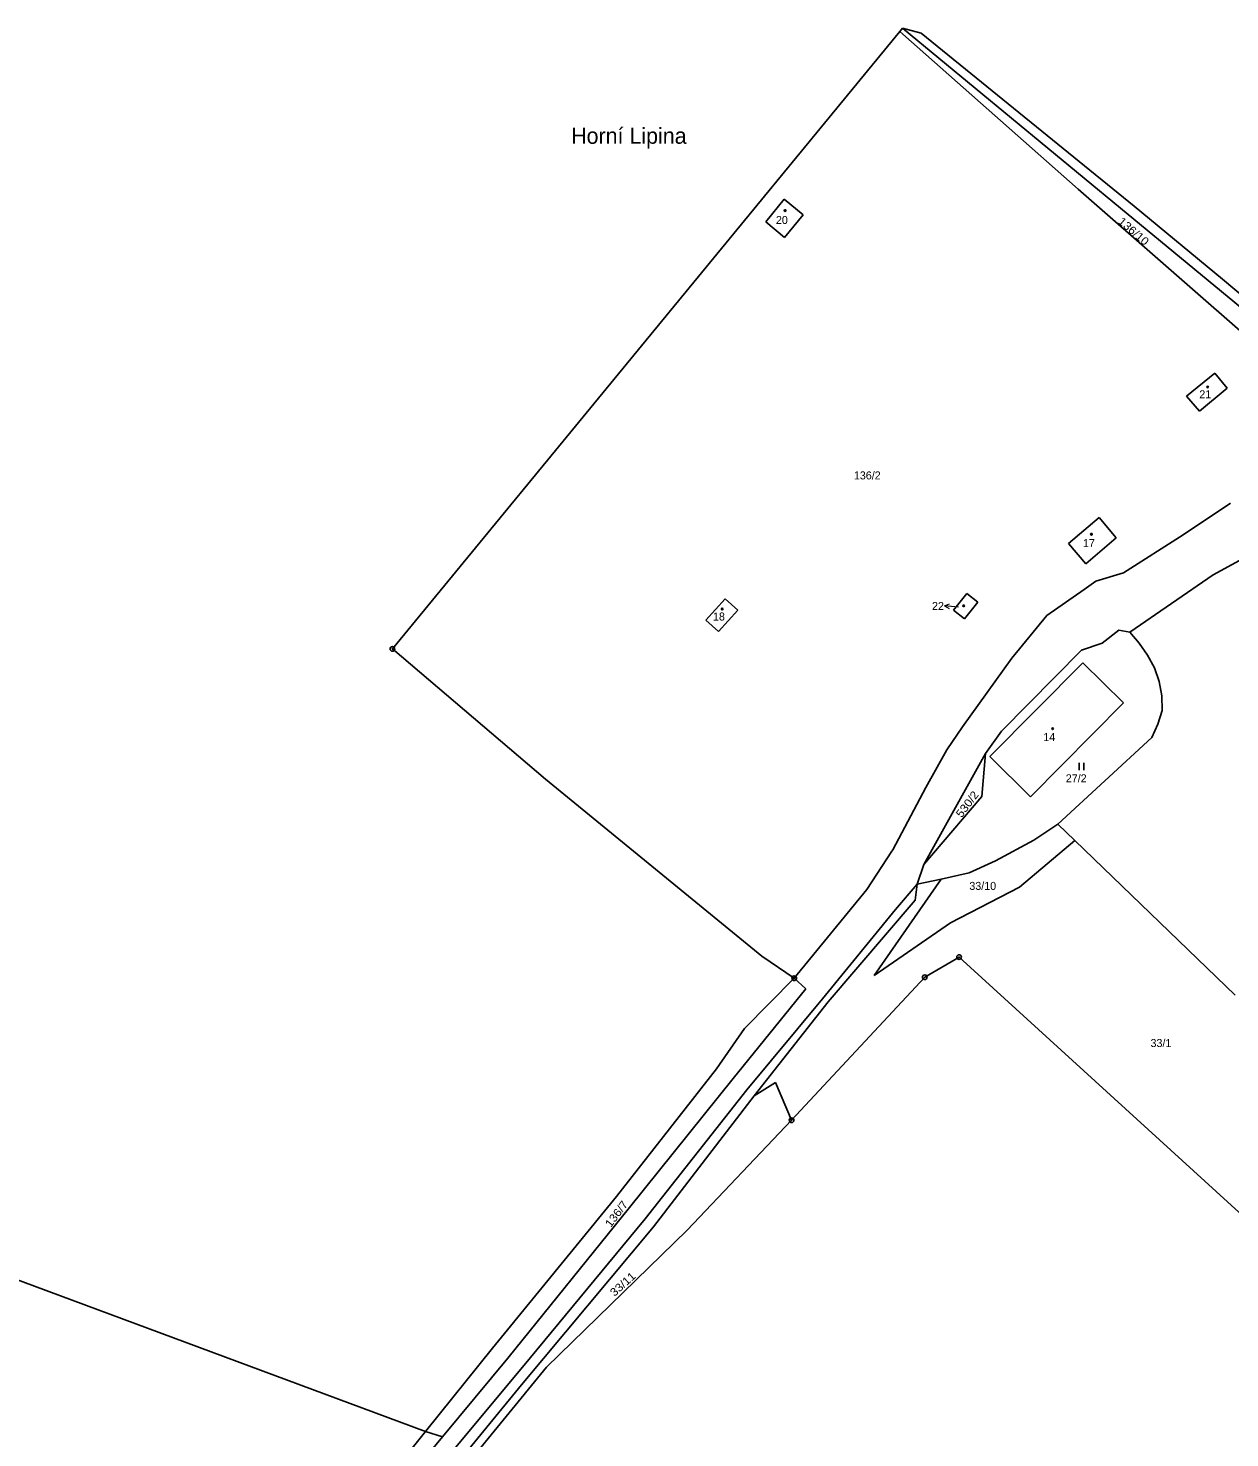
# Model space of a CAD drawing. Extents: x -885985 to -883535, y -1030025 to -1027941.
# Drawn here: x -884995.2 to -884740.1, y -1028620.8 to -1028321.4 of the extents above; entities that cross this region are included whole.
import ezdxf
from ezdxf.enums import TextEntityAlignment as Align

# ---------------------------------------------------------------- set-up
doc = ezdxf.new("R2010")
doc.units = 0
doc.header["$LTSCALE"] = 0.68
for name, color, linetype, lineweight in [('1', 7, 'Continuous', 25), ('3', 7, 'Continuous', 25), ('5', 7, 'Continuous', 25), ('7', 7, 'Continuous', 13), ('8', 7, 'Continuous', 25)]:
    doc.layers.add(name, color=color, linetype=linetype, lineweight=lineweight)
doc.layers.add('2', color=7, linetype='Continuous')

msp = doc.modelspace()

# ---------------------------------------------------------------- linework, layer by layer
at = {"layer": '1'}
for p, q in [((-884810.16, -1028322.13), (-884917.89, -1028453.24)), ((-884809.57, -1028321.41), (-884810.16, -1028322.13)), ((-884809.5, -1028322.71), (-884810.16, -1028322.13)), ((-884763.34, -1028359.63), (-884809.57, -1028321.41)), ((-884805.65, -1028322.44), (-884809.57, -1028321.41)), ((-884772.29, -1028355.57), (-884809.5, -1028322.71)), ((-884760.41, -1028359.24), (-884805.65, -1028322.44)), ((-884729.52, -1028393.05), (-884772.29, -1028355.57)), ((-884834.7, -1028357.7), (-884838.63, -1028362.54)), ((-884830.71, -1028361.02), (-884834.7, -1028357.7)), ((-884834.64, -1028365.83), (-884830.71, -1028361.02)), ((-884726.38, -1028390.13), (-884763.34, -1028359.63)), ((-884741.68, -1028374.7), (-884760.41, -1028359.24)), ((-884838.63, -1028362.54), (-884834.64, -1028365.83)), ((-884731.39, -1028383.37), (-884741.68, -1028374.7)), ((-884743.28, -1028394.66), (-884749.29, -1028399.57)), ((-884740.64, -1028397.87), (-884743.28, -1028394.66)), ((-884749.29, -1028399.57), (-884746.56, -1028402.74)), ((-884746.56, -1028402.74), (-884740.64, -1028397.87)), ((-884750, -1028428.98), (-884739.96, -1028422.25)), ((-884767.87, -1028425.31), (-884774.38, -1028430.81)), ((-884764.24, -1028429.62), (-884767.87, -1028425.31)), ((-884770.7, -1028435.13), (-884764.24, -1028429.62)), ((-884762.67, -1028437.08), (-884750, -1028428.98)), ((-884774.38, -1028430.81), (-884770.7, -1028435.13)), ((-884732.52, -1028431.41), (-884743.63, -1028437.5)), ((-884770.99, -1028440.61), (-884768.57, -1028438.85)), ((-884768.57, -1028438.85), (-884762.67, -1028437.08)), ((-884743.63, -1028437.5), (-884761.32, -1028449.7)), ((-884847.27, -1028442.62), (-884851.36, -1028447.12)), ((-884844.56, -1028445), (-884847.27, -1028442.62)), ((-884795.95, -1028441.47), (-884798.74, -1028444.97)), ((-884793.62, -1028443.28), (-884795.95, -1028441.47)), ((-884778.95, -1028446.13), (-884770.99, -1028440.61)), ((-884848.68, -1028449.55), (-884844.56, -1028445)), ((-884798.74, -1028444.97), (-884796.4, -1028446.82)), ((-884796.4, -1028446.82), (-884793.62, -1028443.28)), ((-884851.36, -1028447.12), (-884848.68, -1028449.55)), ((-884786.36, -1028455.18), (-884778.95, -1028446.13)), ((-884763.65, -1028449.23), (-884767.18, -1028451.98)), ((-884761.32, -1028449.7), (-884763.65, -1028449.23)), ((-884761.32, -1028449.7), (-884759.32, -1028452.04)), ((-884917.89, -1028453.24), (-884885.39, -1028480.9)), ((-884771.6, -1028453.51), (-884788.55, -1028470.67)), ((-884767.18, -1028451.98), (-884771.6, -1028453.51)), ((-884759.32, -1028452.04), (-884757.6, -1028454.57)), ((-884757.6, -1028454.57), (-884756.11, -1028457.28)), ((-884796.83, -1028469.75), (-884786.36, -1028455.18)), ((-884771.27, -1028456.17), (-884791.07, -1028476.09)), ((-884762.66, -1028464.7), (-884771.27, -1028456.17)), ((-884756.11, -1028457.28), (-884755.1, -1028460.17)), ((-884755.1, -1028460.17), (-884754.56, -1028463.21)), ((-884754.56, -1028463.21), (-884754.43, -1028466.29)), ((-884782.43, -1028484.67), (-884762.66, -1028464.7)), ((-884754.43, -1028466.29), (-884755.37, -1028469.19)), ((-884755.37, -1028469.19), (-884756.65, -1028472.05)), ((-884800.18, -1028474.66), (-884796.83, -1028469.75)), ((-884788.55, -1028470.67), (-884791.94, -1028475.42)), ((-884756.65, -1028472.05), (-884776.58, -1028490.47)), ((-884791.94, -1028475.42), (-884805.06, -1028498.98)), ((-884804.62, -1028482.65), (-884800.18, -1028474.66)), ((-884791.94, -1028475.42), (-884792.78, -1028484.57)), ((-884791.07, -1028476.09), (-884782.43, -1028484.67)), ((-884885.39, -1028480.9), (-884839.44, -1028518.48)), ((-884811.62, -1028495.89), (-884804.62, -1028482.65)), ((-884792.78, -1028484.57), (-884805.06, -1028498.98)), ((-884781.72, -1028493.83), (-884776.58, -1028490.47)), ((-884776.58, -1028490.47), (-884773, -1028493.92)), ((-884817.16, -1028504.31), (-884811.82, -1028496.17)), ((-884811.82, -1028496.17), (-884811.62, -1028495.89)), ((-884789.82, -1028498.26), (-884781.72, -1028493.83)), ((-884784.74, -1028503.83), (-884773, -1028493.92)), ((-884773, -1028493.92), (-884738.95, -1028526.77)), ((-884805.06, -1028498.98), (-884806.49, -1028503.2)), ((-884795.44, -1028500.77), (-884789.82, -1028498.26)), ((-884801.38, -1028502.14), (-884815.63, -1028522.55)), ((-884806.49, -1028503.2), (-884801.38, -1028502.14)), ((-884801.38, -1028502.14), (-884795.44, -1028500.77)), ((-884832.58, -1028523.15), (-884817.16, -1028504.31)), ((-884811.05, -1028508.57), (-884806.49, -1028503.2)), ((-884806.92, -1028506.57), (-884806.49, -1028503.2)), ((-884799.37, -1028511.43), (-884784.74, -1028503.83)), ((-884826.57, -1028527.53), (-884811.05, -1028508.57)), ((-884825.38, -1028528.2), (-884806.92, -1028506.57)), ((-884815.63, -1028522.55), (-884799.37, -1028511.43)), ((-884839.44, -1028518.48), (-884832.58, -1028523.15)), ((-884797.58, -1028518.66), (-884804.85, -1028522.96)), ((-884706.28, -1028601.97), (-884797.58, -1028518.66)), ((-884843.11, -1028533.87), (-884832.58, -1028523.15)), ((-884804.85, -1028522.96), (-884833.13, -1028553.32)), ((-884832.58, -1028523.15), (-884830.09, -1028525.42)), ((-884830.09, -1028525.42), (-884845.57, -1028544.42)), ((-884842.67, -1028546.88), (-884826.57, -1028527.53)), ((-884841.05, -1028548.12), (-884825.38, -1028528.2)), ((-884849.05, -1028542.42), (-884843.11, -1028533.87)), ((-884870.33, -1028569.52), (-884849.05, -1028542.42)), ((-884845.57, -1028544.42), (-884867.53, -1028571.86)), ((-884864.21, -1028574.29), (-884842.67, -1028546.88)), ((-884836.58, -1028545.29), (-884841.05, -1028548.12)), ((-884833.13, -1028553.32), (-884836.58, -1028545.29)), ((-884841.05, -1028548.12), (-884862.44, -1028575.92)), ((-885091.71, -1028552.18), (-884910.84, -1028619.42)), ((-884855.28, -1028576.65), (-884833.13, -1028553.32)), ((-884896.63, -1028601.69), (-884870.33, -1028569.52)), ((-884867.53, -1028571.86), (-884893.35, -1028603.81)), ((-884890.29, -1028605.73), (-884864.21, -1028574.29)), ((-884862.44, -1028575.92), (-884890.45, -1028609.52)), ((-884885.14, -1028605.75), (-884855.28, -1028576.65)), ((-884910.84, -1028619.42), (-884896.63, -1028601.69)), ((-884893.35, -1028603.81), (-884907.24, -1028620.55)), ((-884916.48, -1028637.22), (-884890.29, -1028605.73)), ((-884912.96, -1028639.75), (-884885.14, -1028605.75)), ((-884890.45, -1028609.52), (-884914.37, -1028638.65)), ((-884921.91, -1028633.2), (-884910.84, -1028619.42)), ((-884907.24, -1028620.55), (-884919.27, -1028635.04)), ((-884907.24, -1028620.55), (-884910.84, -1028619.42))]:
    msp.add_line(p, q, dxfattribs=at)
at = {"layer": '3'}
for p, q in [((-884772.111, -1028478.95), (-884772.111, -1028477.45)), ((-884771.11, -1028478.95), (-884771.11, -1028477.45))]:
    msp.add_line(p, q, dxfattribs=at)
at = {"layer": '5'}
for centre in [(-884834.5068, -1028360.1392), (-884744.8168, -1028397.6092), (-884769.4668, -1028428.8692), (-884847.8568, -1028444.7392), (-884796.5968, -1028444.0792), (-884777.7068, -1028470.1792)]:
    msp.add_circle(centre, 0.175, dxfattribs=at)
at = {"layer": '7'}
msp.add_line((-884800.655, -1028444.066), (-884799.711, -1028444.669), dxfattribs=at)
msp.add_lwpolyline([(-884797.67, -1028444.38), (-884800.655, -1028444.066), (-884799.606, -1028443.673)], dxfattribs=at)
at = {"layer": '8'}
for centre, radius in [((-884917.89, -1028453.2399), 0.5), ((-884917.89, -1028453.2399), 0.0303), ((-884797.58, -1028518.6599), 0.5), ((-884797.58, -1028518.6599), 0.0303), ((-884832.58, -1028523.1499), 0.5), ((-884832.58, -1028523.1499), 0.0303), ((-884804.85, -1028522.9599), 0.5), ((-884804.85, -1028522.9599), 0.0303), ((-884833.13, -1028553.3199), 0.5), ((-884833.13, -1028553.3199), 0.0303)]:
    msp.add_circle(centre, radius, dxfattribs=at)

# ---------------------------------------------------------------- texts
at = {"layer": '2'}
for s, p in [('20', (-884836.46, -1028362.985)), ('21', (-884746.58, -1028400.005)), ('136/2', (-884819.91, -1028417.235)), ('17', (-884771.28, -1028431.615)), ('18', (-884849.82, -1028447.195)), ('14', (-884779.7, -1028472.795)), ('27/2', (-884774.92, -1028481.555)), ('33/10', (-884795.4, -1028504.405)), ('33/1', (-884756.93, -1028537.775))]:
    msp.add_text(s, height=1.7, dxfattribs=at).set_placement(p)
at = {"layer": '2', "width": 1.1}
for s, rotation, p in [('136/10', 319, (-884763.958, -1028362.68)), ('530/2', 53, (-884797.05, -1028489.215)), ('136/7', 53, (-884871.52, -1028576.225)), ('33/11', 42, (-884870.735, -1028590.845))]:
    msp.add_text(s, height=1.7, rotation=rotation, dxfattribs=at).set_placement(p)
at = {"layer": '2'}
msp.add_text('22', height=1.7, dxfattribs=at).set_placement((-884802.059, -1028444.965), align=Align.CENTER)
at = {"layer": '7'}
msp.add_text('Horní Lipina', height=3.4, dxfattribs=at).set_placement((-884879.94, -1028345.96))

doc.saveas('drawing.dxf')
